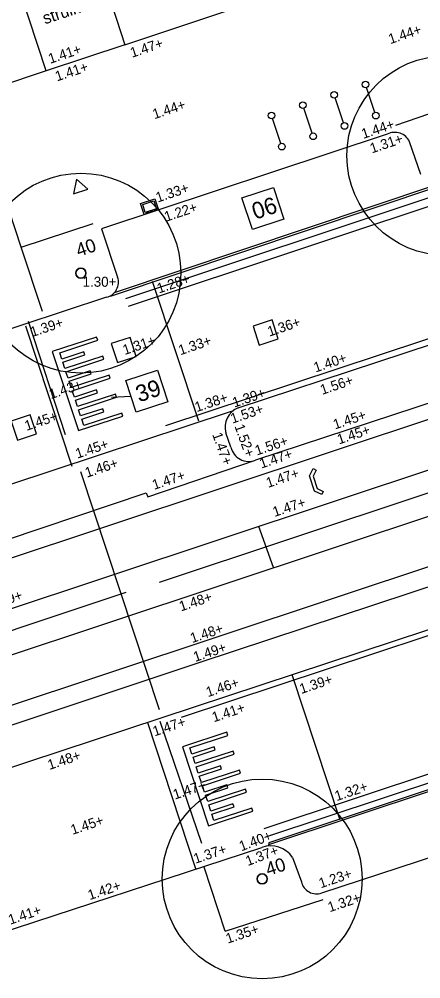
# Model space of a CAD drawing. Extents: x 122462 to 123306, y 485548 to 486417.
# Drawn here: x 122724.72 to 122736.78, y 486139.17 to 486167.98 of the extents above; entities that cross this region are included whole.
import ezdxf

# ---------------------------------------------------------------- set-up
doc = ezdxf.new("R2010")
doc.units = 0
for name, color, linetype in [('B meubilair trammast', 7, 'Continuous'), ('B nummers', 7, 'Continuous'), ('B-WE-AL-T25', 7, 'Continuous'), ('B-WE-GR-BOOM-S', 7, 'Continuous'), ('B-WE-GR-BOOM_BOOMDIAMETER', 7, 'Continuous'), ('B-WE-OG-HOOGTEPUNT-S', 7, 'Continuous'), ('B-WE-OG-TOPOKAART-G', 7, 'Continuous'), ('B-WE-VH-KANTOPSLUITING_OPSLUITBAND_100X200-G', 7, 'Continuous'), ('B-WE-VH-MATERIAALGRENS-G', 7, 'Continuous'), ('V Hoogtelijn', 7, 'Continuous'), ('V markering 1-1 10 cm', 7, 'Continuous'), ('V markering figuratie', 7, 'Continuous'), ('V markering kanalisatiestreep', 7, 'Continuous'), ('V markering ononderbroken streep 10 cm', 7, 'Continuous'), ('V materiaalscheiding algemeen', 7, 'Continuous'), ('V meubilair fietsenrek', 7, 'Continuous'), ('V opsluitband 100x200 mm', 7, 'Continuous'), ('V Rails', 7, 'Continuous'), ('V riool putdeksel', 7, 'Continuous'), ('V riool trottoirkolk', 7, 'Continuous'), ('V RWS-band 115-225x250 mm specie', 7, 'Continuous'), ('V trottoirband 180-200x250 mm specie', 7, 'Continuous')]:
    doc.layers.add(name, color=color, linetype=linetype)

msp = doc.modelspace()

# ---------------------------------------------------------------- linework, layer by layer
at = {"layer": 'B meubilair trammast'}
msp.add_lwpolyline([(122726.354, 486162.743), (122726.781, 486162.884), (122726.445, 486163.184)], close=True, dxfattribs=at)
at = {"layer": 'B nummers'}
msp.add_line((122728.081, 486156.658), (122727.497, 486156.629), dxfattribs=at)
for points in [[(122731.411, 486162.618), (122732.36, 486162.932), (122732.673, 486161.982), (122731.724, 486161.669)], [(122727.924, 486157.133), (122728.874, 486157.446), (122729.187, 486156.497), (122728.237, 486156.183)]]:
    msp.add_lwpolyline(points, close=True, dxfattribs=at)
at = {"layer": 'B-WE-GR-BOOM-S'}
for centre, radius in [((122737.564, 486163.887), 3), ((122726.577, 486160.359), 3), ((122726.577, 486160.359), 0.15), ((122732.019, 486142.169), 3), ((122732.019, 486142.169), 0.15)]:
    msp.add_circle(centre, radius, dxfattribs=at)
for centre, start, end in [((122726.577, 486160.359), 0, 180), ((122726.577, 486160.359), 180, 0), ((122732.019, 486142.169), 0, 180), ((122732.019, 486142.169), 180, 0)]:
    msp.add_arc(centre, 0.15, start, end, dxfattribs=at)
at = {"layer": 'B-WE-OG-TOPOKAART-G'}
msp.add_lwpolyline([(122727.121, 486169.595), (122727.9, 486167.219), (122731.704, 486168.482), (122731.719, 486168.429), (122732.132, 486168.565)], dxfattribs=at)
at = {"layer": 'B-WE-VH-KANTOPSLUITING_OPSLUITBAND_100X200-G'}
msp.add_lwpolyline([(122727.9, 486167.219), (122725.535, 486166.433), (122724.753, 486168.814)], dxfattribs=at)
at = {"layer": 'B-WE-VH-MATERIAALGRENS-G'}
msp.add_line((122725.535, 486166.433), (122716.17, 486163.284), dxfattribs=at)
at = {"layer": 'V Hoogtelijn'}
for points in [[(122730.119, 486155.91), (122728.722, 486160.104)], [(122724.912, 486158.775), (122726.301, 486154.565)], [(122734.355, 486143.965), (122732.917, 486148.298)], [(122728.576, 486146.866), (122730.029, 486142.452)]]:
    msp.add_lwpolyline(points, dxfattribs=at)
at = {"layer": 'V markering 1-1 10 cm'}
for p, q in [((122774.598, 486175.14), (122727.918, 486159.59)), ((122732.076, 486143.681), (122790.419, 486163.059)), ((122732.154, 486143.443), (122744.883, 486147.671))]:
    msp.add_line(p, q, dxfattribs=at)
for points in [[(122774.677, 486174.903), (122727.997, 486159.353)], [(122726.563, 486154.401), (122728.931, 486147.253)], [(122721.302, 486148.563), (122727.94, 486150.784)]]:
    msp.add_lwpolyline(points, dxfattribs=at)
at = {"layer": 'V markering figuratie'}
for p, q in [((122712.845, 486143.511), (122860.885, 486192.728)), ((122727.05, 486158.438), (122725.719, 486158.002)), ((122725.941, 486157.97), (122727.081, 486158.343)), ((122727.081, 486158.343), (122727.05, 486158.438)), ((122725.719, 486158.002), (122726.504, 486155.629)), ((122726.669, 486157.997), (122726.003, 486157.78)), ((122726.7, 486157.902), (122726.669, 486157.997)), ((122726.003, 486157.78), (122725.941, 486157.97)), ((122726.035, 486157.685), (122726.7, 486157.902)), ((122727.238, 486157.867), (122726.098, 486157.494)), ((122726.129, 486157.399), (122727.269, 486157.772)), ((122727.269, 486157.772), (122727.238, 486157.867)), ((122726.098, 486157.494), (122726.035, 486157.685)), ((122726.191, 486157.209), (122726.129, 486157.399)), ((122726.857, 486157.427), (122726.191, 486157.209)), ((122726.888, 486157.332), (122726.857, 486157.427)), ((122726.223, 486157.115), (122726.888, 486157.332)), ((122726.286, 486156.924), (122726.223, 486157.115)), ((122727.426, 486157.297), (122726.286, 486156.924)), ((122726.318, 486156.829), (122727.457, 486157.202)), ((122727.457, 486157.202), (122727.426, 486157.297)), ((122726.38, 486156.639), (122726.318, 486156.829)), ((122727.045, 486156.857), (122726.38, 486156.639)), ((122727.076, 486156.762), (122727.045, 486156.857)), ((122726.412, 486156.545), (122727.076, 486156.762)), ((122726.475, 486156.354), (122726.412, 486156.545)), ((122727.614, 486156.727), (122726.475, 486156.354)), ((122726.506, 486156.259), (122727.645, 486156.632)), ((122727.645, 486156.632), (122727.614, 486156.727)), ((122726.568, 486156.071), (122726.506, 486156.259)), ((122727.234, 486156.288), (122726.568, 486156.071)), ((122727.265, 486156.193), (122727.234, 486156.288)), ((122726.504, 486155.629), (122727.834, 486156.064)), ((122726.6, 486155.976), (122727.265, 486156.193)), ((122726.663, 486155.786), (122726.6, 486155.976)), ((122727.803, 486156.159), (122726.663, 486155.786)), ((122727.834, 486156.064), (122727.803, 486156.159)), ((122733.439, 486154.275), (122733.547, 486154.491)), ((122733.591, 486153.817), (122733.439, 486154.275)), ((122733.547, 486154.491), (122733.637, 486154.446)), ((122733.637, 486154.446), (122733.547, 486154.267)), ((122733.547, 486154.267), (122733.673, 486153.888)), ((122733.807, 486153.709), (122733.591, 486153.817)), ((122733.673, 486153.888), (122733.852, 486153.798)), ((122733.852, 486153.798), (122733.807, 486153.709)), ((122730.958, 486146.575), (122729.628, 486146.14)), ((122729.849, 486146.107), (122730.99, 486146.48)), ((122730.99, 486146.48), (122730.958, 486146.575)), ((122729.628, 486146.14), (122730.412, 486143.766)), ((122729.912, 486145.917), (122729.849, 486146.107)), ((122730.577, 486146.135), (122729.912, 486145.917)), ((122729.943, 486145.822), (122730.609, 486146.04)), ((122731.146, 486146.005), (122730.006, 486145.632)), ((122730.037, 486145.537), (122731.178, 486145.91)), ((122730.609, 486146.04), (122730.577, 486146.135)), ((122731.178, 486145.91), (122731.146, 486146.005)), ((122730.006, 486145.632), (122729.943, 486145.822)), ((122730.1, 486145.347), (122730.037, 486145.537)), ((122730.765, 486145.565), (122730.1, 486145.347)), ((122730.131, 486145.252), (122730.797, 486145.47)), ((122731.334, 486145.435), (122730.194, 486145.062)), ((122730.226, 486144.967), (122731.366, 486145.34)), ((122730.797, 486145.47), (122730.765, 486145.565)), ((122731.366, 486145.34), (122731.334, 486145.435)), ((122730.194, 486145.062), (122730.131, 486145.252)), ((122730.289, 486144.777), (122730.226, 486144.967)), ((122730.953, 486144.995), (122730.289, 486144.777)), ((122730.32, 486144.682), (122730.984, 486144.9)), ((122731.522, 486144.865), (122730.383, 486144.492)), ((122730.414, 486144.397), (122731.553, 486144.77)), ((122730.984, 486144.9), (122730.953, 486144.995)), ((122731.553, 486144.77), (122731.522, 486144.865)), ((122730.383, 486144.492), (122730.32, 486144.682)), ((122730.412, 486143.766), (122731.743, 486144.202)), ((122730.477, 486144.208), (122730.414, 486144.397)), ((122731.142, 486144.426), (122730.477, 486144.208)), ((122730.508, 486144.113), (122731.174, 486144.331)), ((122731.712, 486144.297), (122730.571, 486143.923)), ((122731.174, 486144.331), (122731.142, 486144.426)), ((122731.743, 486144.202), (122731.712, 486144.297)), ((122730.571, 486143.923), (122730.508, 486144.113))]:
    msp.add_line(p, q, dxfattribs=at)
at = {"layer": 'V markering kanalisatiestreep'}
for p, q in [((122724.994, 486158.915), (122726.107, 486155.513)), ((122728.945, 486146.905), (122730.198, 486143.24))]:
    msp.add_line(p, q, dxfattribs=at)
at = {"layer": 'V markering ononderbroken streep 10 cm'}
msp.add_line((122737.222, 486162.996), (122727.575, 486159.765), dxfattribs=at)
for points in [[(122782.506, 486173.456), (122769.669, 486169.188), (122753.621, 486163.883), (122729.113, 486155.773)], [(122728.941, 486151.077), (122760.57, 486161.6), (122777.147, 486167.134), (122788.89, 486171.042)], [(122790.431, 486167.268), (122783.519, 486164.927), (122758.686, 486156.675), (122742.703, 486151.362), (122729.592, 486147.018)], [(122744.749, 486147.36), (122732.209, 486143.188)]]:
    msp.add_lwpolyline(points, dxfattribs=at)
at = {"layer": 'V materiaalscheiding algemeen'}
for p, q in [((122724.787, 486161.134), (122723.306, 486165.627)), ((122730.909, 486140.598), (122733.846, 486141.549))]:
    msp.add_line(p, q, dxfattribs=at)
for points in [[(122780.156, 486165.287), (122764.259, 486160.016), (122760.446, 486158.724), (122755.663, 486157.161), (122747.256, 486154.337), (122738.577, 486151.45), (122730.117, 486148.653), (122721.549, 486145.803), (122712.998, 486142.94), (122707.935, 486141.266)], [(122737.346, 486162.974), (122727.454, 486159.661)], [(122706.259, 486146.355), (122714.713, 486149.163), (122723.288, 486152.002), (122728.54, 486153.762), (122728.584, 486153.641), (122731.819, 486154.741)], [(122744.769, 486147.43), (122732.216, 486143.253), (122732.207, 486143.158)]]:
    msp.add_lwpolyline(points, dxfattribs=at)
at = {"layer": 'V meubilair fietsenrek'}
for p, q in [((122735.4, 486165.184), (122735.152, 486165.93)), ((122734.459, 486164.874), (122734.212, 486165.62)), ((122733.52, 486164.563), (122733.273, 486165.309)), ((122732.58, 486164.252), (122732.333, 486164.999))]:
    msp.add_line(p, q, dxfattribs=at)
for centre in [(122735.121, 486166.025), (122734.181, 486165.715), (122733.241, 486165.404), (122732.301, 486165.094), (122735.431, 486165.089), (122734.491, 486164.779), (122733.551, 486164.468), (122732.611, 486164.157)]:
    msp.add_circle(centre, 0.1, dxfattribs=at)
at = {"layer": 'V opsluitband 100x200 mm'}
for points in [[(122736.032, 486164.805), (122738.398, 486165.618)], [(122725.421, 486159.203), (122724.787, 486161.134), (122726.95, 486161.852)]]:
    msp.add_lwpolyline(points, dxfattribs=at)
at = {"layer": 'V Rails'}
for p, q in [((122714.919, 486148.627), (122859.557, 486196.72)), ((122715.373, 486147.26), (122860.011, 486195.354)), ((122712.39, 486144.878), (122860.43, 486194.095))]:
    msp.add_line(p, q, dxfattribs=at)
msp.add_lwpolyline([(122732.356, 486151.523), (122731.92, 486152.755)], dxfattribs=at)
at = {"layer": 'V riool putdeksel'}
for points in [[(122731.933, 486158.195), (122732.503, 486158.383), (122732.315, 486158.953), (122731.745, 486158.765)], [(122727.671, 486157.672), (122728.241, 486157.86), (122728.053, 486158.43), (122727.483, 486158.242)], [(122724.673, 486155.348), (122725.243, 486155.536), (122725.055, 486156.106), (122724.485, 486155.918)]]:
    msp.add_lwpolyline(points, close=True, dxfattribs=at)
at = {"layer": 'V riool trottoirkolk'}
for p, q in [((122728.369, 486162.451), (122728.796, 486162.592)), ((122728.796, 486162.592), (122728.906, 486162.26)), ((122728.479, 486162.118), (122728.369, 486162.451)), ((122728.906, 486162.26), (122728.479, 486162.118)), ((122728.527, 486162.134), (122728.525, 486162.139)), ((122728.607, 486162.176), (122728.531, 486162.151)), ((122728.622, 486162.165), (122728.62, 486162.17)), ((122728.645, 486162.173), (122728.644, 486162.178)), ((122728.726, 486162.216), (122728.65, 486162.191)), ((122728.74, 486162.205), (122728.739, 486162.209)), ((122728.764, 486162.213), (122728.762, 486162.217)), ((122728.8, 486162.24), (122728.769, 486162.23)), ((122728.845, 486162.255), (122728.8, 486162.24)), ((122728.859, 486162.244), (122728.857, 486162.249))]:
    msp.add_line(p, q, dxfattribs=at)
msp.add_lwpolyline([(122728.432, 486162.419), (122728.765, 486162.529), (122728.843, 486162.291), (122728.511, 486162.181)], close=True, dxfattribs=at)
for centre, start, end in [((122728.535, 486162.142), 108.3049, 198.3049), ((122728.61, 486162.167), 18.3049, 108.3049), ((122728.653, 486162.181), 108.3049, 198.3049), ((122728.729, 486162.206), 18.3049, 108.3049), ((122728.772, 486162.22), 108.3049, 198.3049), ((122728.848, 486162.246), 18.3049, 108.3049)]:
    msp.add_arc(centre, 0.01, start, end, dxfattribs=at)
at = {"layer": 'V RWS-band 115-225x250 mm specie'}
for points in [[(122788.059, 486166.632), (122787.124, 486166.306), (122785.206, 486165.623), (122777.128, 486162.968), (122760.015, 486157.342), (122740.955, 486150.951), (122719.987, 486144.031), (122708.301, 486140.155)], [(122705.772, 486147.833), (122731.103, 486156.21)]]:
    msp.add_lwpolyline(points, dxfattribs=at)
at = {"layer": 'V trottoirband 180-200x250 mm specie'}
for points in [[(122802.843, 486178.897), (122803.005, 486178.403), (122796.653, 486176.321), (122790.145, 486174.137), (122787.981, 486173.414), (122783.643, 486171.985), (122782.562, 486171.633), (122774.188, 486168.85), (122765.631, 486166.001), (122757.287, 486163.217), (122748.482, 486160.287), (122740.076, 486157.459), (122731.818, 486154.747)], [(122731.297, 486156.319), (122739.679, 486159.075), (122748.36, 486161.956), (122756.611, 486164.69), (122764.995, 486167.464)], [(122735.776, 486164.532), (122727.198, 486161.694), (122727.679, 486160.24)], [(122736.781, 486163.324), (122736.446, 486164.303)], [(122727.346, 486159.635), (122714.629, 486155.437)], [(122731.079, 486155.133), (122730.926, 486155.56)], [(122733.81, 486141.749), (122740.748, 486144.02), (122744.67, 486145.313)], [(122722.92, 486140.139), (122732.01, 486143.108)], [(122732.928, 486142.809), (122733.195, 486142.08)], [(122730.909, 486140.598), (122730.279, 486142.519)]]:
    msp.add_lwpolyline(points, dxfattribs=at)
for centre, radius, start, end in [((122735.998, 486164.087), 0.498, 25.7638, 116.4962), ((122727.241, 486160.087), 0.464, 283.0782, 19.2639), ((122731.562, 486155.719), 0.656, 113.8427, 194.0584), ((122731.612, 486155.254), 0.547, 192.7708, 292.0706), ((122732.292, 486142.416), 0.748, 31.7434, 112.1749), ((122733.651, 486142.19), 0.469, 193.525, 289.8957)]:
    msp.add_arc(centre, radius, start, end, dxfattribs=at)

# ---------------------------------------------------------------- texts
at = {"layer": 'B nummers'}
for s, p in [('06', (122731.809, 486161.96)), ('39', (122728.322, 486156.475))]:
    msp.add_text(s, height=0.5, rotation=18.2603, dxfattribs=at).set_placement(p)
at = {"layer": 'B-WE-AL-T25'}
msp.add_text('struiken', height=0.36, rotation=18.3134, dxfattribs=at).set_placement((122725.497, 486167.828))
at = {"layer": 'B-WE-GR-BOOM_BOOMDIAMETER'}
for rotation, p in [(18.7219, (122726.509, 486160.844)), (17.9781, (122732.199, 486142.256))]:
    msp.add_text('40', height=0.4, rotation=rotation, dxfattribs=at).set_placement(p)
at = {"layer": 'B-WE-OG-HOOGTEPUNT-S'}
for s, rotation, p in [('1.44+', 18.2611, (122735.865, 486167.235)), ('1.47+', 18.3766, (122728.113, 486166.824)), ('1.41+', 18.3766, (122725.655, 486166.644)), ('1.41+', 18.3766, (122725.861, 486166.115)), ('1.44+', 18.3766, (122728.785, 486164.98)), ('1.44+', 18.5166, (122735.056, 486164.387)), ('1.31+', 18.5166, (122735.312, 486163.954)), ('1.33+', 18.3766, (122728.883, 486162.478)), ('1.22+', 18.3766, (122729.137, 486161.901)), ('1.28+', 18.4074, (122728.919, 486159.747)), ('1.39+', 18.2685, (122725.114, 486158.437)), ('1.36+', 18.4074, (122732.235, 486158.451)), ('1.31+', 18.5166, (122727.89, 486157.899)), ('1.33+', 18.4074, (122729.562, 486157.893)), ('1.40+', 18.4074, (122733.622, 486157.374)), ('1.56+', 18.5884, (122733.82, 486156.702)), ('1.43+', 18.2685, (122725.679, 486156.574)), ('1.39+', 18.5941, (122731.183, 486156.32)), ('1.38+', 18.4074, (122730.053, 486156.183)), ('1.53+', 18.5941, (122731.125, 486155.838)), ('1.45+', 18.2685, (122724.944, 486155.622)), ('1.45+', 18.4023, (122734.206, 486155.663)), ('1.52+', 289.7133, (122731.184, 486155.765)), ('1.45+', 18.4023, (122734.327, 486155.214)), ('1.47+', 289.7133, (122730.515, 486155.516)), ('1.56+', 18.5884, (122731.86, 486154.881)), ('1.45+', 18.4226, (122726.471, 486154.788)), ('1.47+', 18.5884, (122731.994, 486154.489)), ('1.46+', 18.4226, (122726.758, 486154.216)), ('1.47+', 18.4226, (122728.775, 486153.849)), ('1.47+', 18.5884, (122732.195, 486153.909)), ('1.47+', 18.4023, (122732.391, 486153.036)), ('1.49+', 18.4015, (122723.89, 486150.248)), ('1.48+', 18.3718, (122729.583, 486150.2)), ('1.48+', 18.3718, (122729.916, 486149.248)), ('1.49+', 18.4023, (122730.009, 486148.683)), ('1.39+', 18.3738, (122733.195, 486147.721)), ('1.46+', 18.4023, (122730.39, 486147.625)), ('1.41+', 18.3738, (122730.569, 486146.872)), ('1.47+', 18.3738, (122728.789, 486146.447)), ('1.48+', 18.3738, (122725.635, 486145.441)), ('1.47+', 18.3738, (122729.398, 486144.55)), ('1.32+', 18.3738, (122734.254, 486144.503)), ('1.45+', 18.3738, (122726.326, 486143.49)), ('1.40+', 20.5818, (122731.392, 486142.996)), ('1.37+', 18.3738, (122730.016, 486142.623)), ('1.37+', 20.5818, (122731.587, 486142.552)), ('1.23+', 18.3738, (122733.777, 486141.885)), ('1.42+', 18.3738, (122726.842, 486141.53)), ('1.32+', 18.3738, (122734.046, 486141.167)), ('1.41+', 18.3738, (122724.455, 486140.792)), ('1.35+', 18.3738, (122730.984, 486140.223))]:
    msp.add_text(s, height=0.3, rotation=rotation, dxfattribs=at).set_placement(p)
msp.add_text('1.30+', height=0.3, dxfattribs=at).set_placement((122726.628, 486159.95))

doc.saveas('drawing.dxf')
